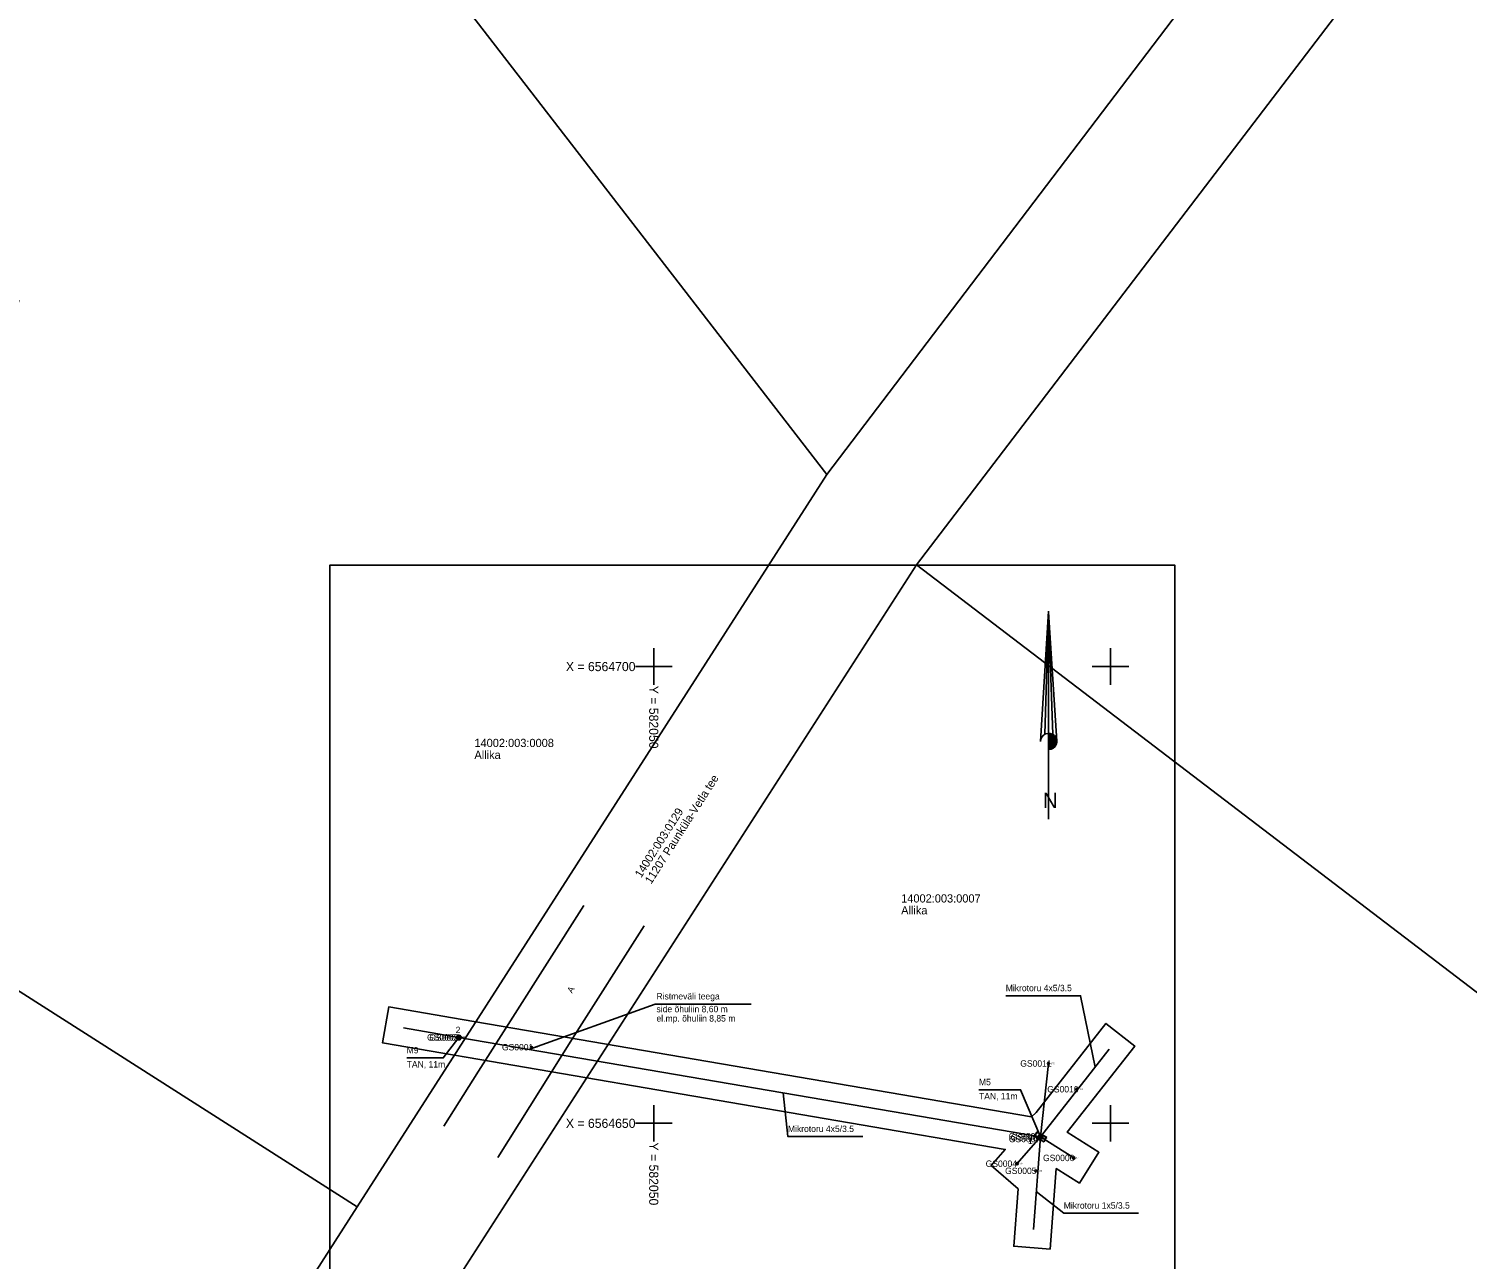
# Model space of a CAD drawing. Extents: x 579747 to 582499, y 6562295 to 6565613.
# Drawn here: x 581981.6 to 582139.1, y 6564635.1 to 6564769.8 of the extents above; entities that cross this region are included whole.
import ezdxf

# ---------------------------------------------------------------- set-up
doc = ezdxf.new("R2010")
doc.units = 0
for name, color, linetype in [('ABIJOONIS', 7, 'Continuous'), ('ELRAJATISMP', 7, 'Continuous'), ('KOORDPUNKT', 7, 'Continuous'), ('MOOTKORG-EH2000', 7, 'Continuous'), ('MOOTMPUNKT', 7, 'Continuous'), ('MOOTNR', 7, 'Continuous'), ('MOOTPIIR', 7, 'Continuous'), ('MPOHULIIN', 7, 'Continuous'), ('PIIR', 7, 'Continuous'), ('POST', 7, 'Continuous'), ('SIOHULIIN', 7, 'Continuous'), ('TEE', 7, 'Continuous'), ('VORK', 7, 'Continuous'), ('VORMISTUS', 7, 'Continuous')]:
    doc.layers.add(name, color=color, linetype=linetype)

msp = doc.modelspace()

# ---------------------------------------------------------------- linework, layer by layer
at = {"layer": 'ELRAJATISMP'}
for p, q in [((582092.36, 6564648.84), (582092.07, 6564648.33)), ((582092.6, 6564648.71), (582092.3, 6564648.19))]:
    msp.add_line(p, q, dxfattribs=at)
msp.add_lwpolyline([(582091.96, 6564649.07), (582093, 6564648.48), (582092.7, 6564647.96), (582091.67, 6564648.55)], close=True, dxfattribs=at)
at = {"layer": 'KOORDPUNKT'}
for centre, radius in [((582028.67, 6564659.4), 0.188), ((582028.67, 6564659.4), 0.0143), ((582028.67, 6564659.4), 0.0165), ((582028.67, 6564659.4), 0.0188), ((582028.67, 6564659.4), 0.00323), ((582028.67, 6564659.4), 0.00545), ((582028.67, 6564659.4), 0.00766), ((582028.67, 6564659.4), 0.00988), ((582028.67, 6564659.4), 0.0121), ((582092.33, 6564648.52), 0.188), ((582092.33, 6564648.52), 0.0188), ((582092.33, 6564648.52), 0.00988), ((582092.33, 6564648.52), 0.0121), ((582092.33, 6564648.52), 0.0143), ((582092.33, 6564648.52), 0.0165), ((582092.33, 6564648.52), 0.00766), ((582092.33, 6564648.52), 0.00323), ((582092.33, 6564648.52), 0.00545)]:
    msp.add_circle(centre, radius, dxfattribs=at)
at = {"layer": 'MOOTMPUNKT'}
for centre in [(582028.54, 6564659.41), (582028.67, 6564659.4), (582028.79, 6564659.39), (582036.6, 6564658.33), (582093.21, 6564656.55), (582096.3, 6564653.73), (582092.23, 6564648.59), (582092.24, 6564648.28), (582092.33, 6564648.52), (582092.44, 6564648.45), (582095.98, 6564646.21), (582089.76, 6564645.58), (582091.83, 6564644.8)]:
    msp.add_circle(centre, 0.1, dxfattribs=at)
at = {"layer": 'MOOTPIIR'}
msp.add_lwpolyline([(582029.01, 6564661.37), (582091.35, 6564650.72), (582091.87, 6564651.18), (582099.51, 6564660.93), (582102.66, 6564658.46), (582095.27, 6564649.03), (582098.74, 6564646.83), (582096.6, 6564643.45), (582094.07, 6564645.05), (582093.4, 6564636.23), (582089.41, 6564636.54), (582089.89, 6564642.81), (582086.94, 6564645.39), (582088.48, 6564647.15), (582020.31, 6564658.81), (582020.99, 6564662.75)], close=True, dxfattribs=at)
at = {"layer": 'MPOHULIIN'}
for p, q in [((582092.33, 6564648.52), (582099.85, 6564658.12)), ((582093.21, 6564656.55), (582092.33, 6564648.52)), ((582092.33, 6564648.52), (582091.56, 6564638.38))]:
    msp.add_line(p, q, dxfattribs=at)
msp.add_lwpolyline([(582092.33, 6564648.52), (582028.67, 6564659.4), (582022.62, 6564660.44)], dxfattribs=at)
at = {"layer": 'PIIR'}
for points in [[(581663.3, 6564864.5), (581668.6, 6564818), (581873.54, 6564758.6), (581980.49, 6564740.06), (581961.05, 6564676.89), (582017.54, 6564640.84), (582068.96, 6564721.02), (581983.85, 6564831.15), (581889.63, 6565244.18), (581674.18, 6565307.14)], [(582078.75, 6564711.15), (582029.16, 6564634.01), (582192.43, 6564520.86), (582199.06, 6564516.3), (582287.58, 6564527.55), (582301.82, 6564540.75), (582292.62, 6564547.98)]]:
    msp.add_lwpolyline(points, close=True, dxfattribs=at)
for points in [[(582135.55, 6564808.67), (582068.96, 6564721.02), (582017.54, 6564640.84), (581956.73, 6564546.01), (581888.98, 6564444.16), (581819.5, 6564352.29), (581772.04, 6564298.67), (581650.74, 6564171.18), (581565.74, 6564073.89), (581521.68, 6564027.95), (581462.2, 6563979.51), (581405.77, 6563949.46), (581387.54, 6563937.32), (581346.36, 6563914.86)], [(581384.59, 6563917.2), (581404.32, 6563931.05), (581456.61, 6563960.43), (581471.37, 6563968.93), (581531.08, 6564017.57), (581575.85, 6564064.19), (581579.4, 6564062.41), (581615.32, 6564103.23), (581653.52, 6564150.59), (581684.72, 6564185.3), (581762.65, 6564266.98), (581831.7, 6564341.91), (581902.22, 6564435.18), (581985.17, 6564563.48), (582029.16, 6564634.01), (582078.75, 6564711.15), (582146.74, 6564800.25)]]:
    msp.add_lwpolyline(points, dxfattribs=at)
at = {"layer": 'POST'}
for points in [[(582028.67, 6564659.4), (582026.95, 6564657.16), (582022.95, 6564657.16)], [(582092.33, 6564648.52), (582090.17, 6564653.67), (582085.61, 6564653.67)], [(582092.33, 6564648.52), (582089.76, 6564645.58)], [(582092.33, 6564648.52), (582095.98, 6564646.21)]]:
    msp.add_lwpolyline(points, dxfattribs=at)
for centre, radius in [((582028.67, 6564659.4), 0.25), ((582092.33, 6564648.52), 0.25), ((582095.98, 6564646.21), 0.125), ((582095.98, 6564646.21), 0.105), ((582095.98, 6564646.21), 0.0851), ((582095.98, 6564646.21), 0.0651), ((582095.98, 6564646.21), 0.0451), ((582095.98, 6564646.21), 0.0251), ((582095.98, 6564646.21), 0.00511), ((582089.76, 6564645.58), 0.125), ((582089.76, 6564645.58), 0.105), ((582089.76, 6564645.58), 0.0851), ((582089.76, 6564645.58), 0.0651), ((582089.76, 6564645.58), 0.0451), ((582089.76, 6564645.58), 0.0251), ((582089.76, 6564645.58), 0.00511)]:
    msp.add_circle(centre, radius, dxfattribs=at)
at = {"layer": 'SIOHULIIN'}
for p, q in [((582092.33, 6564648.52), (582099.85, 6564658.12)), ((582091.56, 6564638.38), (582092.33, 6564648.52))]:
    msp.add_line(p, q, dxfattribs=at)
for points in [[(582098.32, 6564656.16), (582096.73, 6564663.96), (582088.54, 6564663.96)], [(582036.33, 6564658.09), (582050.15, 6564663.06), (582060.68, 6564663.06)], [(582022.62, 6564660.44), (582028.67, 6564659.4), (582092.33, 6564648.52)], [(582064.17, 6564653.33), (582064.69, 6564648.55), (582072.88, 6564648.55)], [(582091.88, 6564642.54), (582094.89, 6564640.16), (582103.08, 6564640.16)]]:
    msp.add_lwpolyline(points, dxfattribs=at)
at = {"layer": 'TEE'}
for points in [[(582042.35, 6564673.85), (582030.81, 6564655.7), (582027.01, 6564649.67)], [(582032.93, 6564646.24), (582041.12, 6564659.29), (582048.95, 6564671.63)]]:
    msp.add_lwpolyline(points, dxfattribs=at)
at = {"layer": 'VORK'}
for p, q in [((582050, 6564702), (582050, 6564698)), ((582100, 6564702), (582100, 6564698)), ((582048, 6564700), (582052, 6564700)), ((582098, 6564700), (582102, 6564700)), ((582050, 6564652), (582050, 6564648)), ((582100, 6564652), (582100, 6564648)), ((582048, 6564650), (582052, 6564650)), ((582098, 6564650), (582102, 6564650))]:
    msp.add_line(p, q, dxfattribs=at)
at = {"layer": 'VORMISTUS'}
msp.add_lwpolyline([(582014.55, 6564568.11), (582014.55, 6564711.11), (582107.05, 6564711.11), (582107.05, 6564568.11)], close=True, dxfattribs=at)
for points in [[(582093.23, 6564706.06), (582092.33, 6564691.8)], [(582093.23, 6564705.96), (582092.81, 6564692.59)], [(582093.22, 6564706.01), (582093.69, 6564692.56)], [(582093.23, 6564706.06), (582093.23, 6564683.31)], [(582093.23, 6564705.95), (582094.12, 6564691.82)], [(582093.23, 6564692.69), (582093.27, 6564692.69)], [(582093.23, 6564692.69), (582093.25, 6564692.69)], [(582093.23, 6564692.59), (582093.66, 6564692.59)], [(582093.23, 6564692.48), (582093.8, 6564692.48)], [(582093.23, 6564692.38), (582093.89, 6564692.38)], [(582093.23, 6564692.28), (582093.97, 6564692.28)], [(582093.23, 6564692.17), (582094.03, 6564692.17)], [(582093.23, 6564692.07), (582094.07, 6564692.07)], [(582093.23, 6564691.97), (582094.1, 6564691.97)], [(582093.23, 6564691.86), (582094.11, 6564691.86)], [(582093.23, 6564691.76), (582094.12, 6564691.76)], [(582093.23, 6564691.66), (582094.1, 6564691.66)], [(582093.23, 6564691.56), (582094.08, 6564691.56)], [(582093.3, 6564690.92), (582093.3, 6564692.68)], [(582093.4, 6564690.94), (582093.4, 6564692.67)], [(582093.51, 6564690.95), (582093.51, 6564692.64)], [(582093.61, 6564691), (582093.61, 6564692.6)], [(582093.71, 6564691.06), (582093.71, 6564692.56)], [(582093.81, 6564691.14), (582093.81, 6564692.47)], [(582093.92, 6564691.24), (582093.92, 6564692.35)], [(582094.02, 6564691.41), (582094.02, 6564692.21)], [(582093.22, 6564690.94), (582093.42, 6564690.94)], [(582093.23, 6564691.45), (582094.04, 6564691.45)], [(582093.23, 6564691.35), (582093.99, 6564691.35)], [(582093.23, 6564691.25), (582093.92, 6564691.25)], [(582093.23, 6564691.14), (582093.82, 6564691.14)], [(582093.23, 6564691.04), (582093.68, 6564691.04)]]:
    msp.add_lwpolyline(points, dxfattribs=at)
msp.add_arc((582093.24, 6564691.8), 0.894, 270.3348, 180.6244, dxfattribs=at)

# ---------------------------------------------------------------- texts
at = {"layer": 'ABIJOONIS'}
for s, p in [(' 2', (582028.05, 6564659.87)), (' 1', (582090.71, 6564647.74))]:
    msp.add_text(s, height=0.7, dxfattribs=at).set_placement(p)
at = {"layer": 'MOOTKORG-EH2000'}
for s, p in [(' 64.84', (582028.54, 6564659.33)), (' 64.83', (582028.67, 6564659.31)), (' 64.82', (582028.79, 6564659.3)), (' 64.89', (582036.6, 6564658.24)), (' 64.79', (582093.21, 6564656.46)), (' 64.93', (582096.3, 6564653.64)), (' 64.97', (582092.23, 6564648.5)), (' 64.99', (582092.24, 6564648.19)), (' 64.99', (582092.33, 6564648.43)), (' 65.00', (582092.44, 6564648.36)), (' 64.91', (582095.98, 6564646.12)), (' 64.84', (582089.76, 6564645.5)), (' 64.83', (582091.83, 6564644.71))]:
    msp.add_text(s, height=0.175, dxfattribs=at).set_placement(p)
at = {"layer": 'MOOTNR'}
for s, p in [('GS0003 ', (582025.18, 6564659.06)), ('GS0002 ', (582025.43, 6564659.04)), ('GS0001 ', (582033.38, 6564657.98)), ('GS0011 ', (582090.13, 6564656.2)), ('GS0010 ', (582093.08, 6564653.38)), ('GS0009 ', (582088.87, 6564648.24)), ('GS0007 ', (582088.88, 6564647.93)), ('GS0008 ', (582089.08, 6564648.1)), ('GS0004 ', (582086.34, 6564645.23)), ('GS0006 ', (582092.62, 6564645.86)), ('GS0005 ', (582088.47, 6564644.45))]:
    msp.add_text(s, height=0.7, dxfattribs=at).set_placement(p)
at = {"layer": 'PIIR'}
for s, p in [('14002:003:0008', (582030.37, 6564691.19)), ('Allika', (582030.37, 6564689.89)), ('14002:003:0007', (582077.09, 6564674.17)), ('Allika', (582077.09, 6564672.87))]:
    msp.add_text(s, height=0.9, dxfattribs=at).set_placement(p)
for s, p in [('11207 Paunküla-Vetla tee', (582049.72, 6564676.12)), ('14002:003:0129', (582048.62, 6564676.81))]:
    msp.add_text(s, height=0.9, rotation=57.5293, dxfattribs=at).set_placement(p)
at = {"layer": 'POST'}
for s, p in [('M9', (582022.95, 6564657.66)), ('TAN, 11m', (582022.95, 6564656.11)), ('M5', (582085.61, 6564654.17)), ('TAN, 11m', (582085.61, 6564652.62))]:
    msp.add_text(s, height=0.7, dxfattribs=at).set_placement(p)
at = {"layer": 'SIOHULIIN'}
for s, p in [('Mikrotoru 4x5/3.5', (582088.54, 6564664.46)), ('Ristmeväli teega', (582050.3, 6564663.56)), ('side õhuliin 8,60 m', (582050.3, 6564662.16)), ('el.mp. õhuliin 8,85 m', (582050.3, 6564661.14)), ('Mikrotoru 4x5/3.5', (582064.69, 6564649.05)), ('Mikrotoru 1x5/3.5', (582094.89, 6564640.66))]:
    msp.add_text(s, height=0.7, dxfattribs=at).set_placement(p)
at = {"layer": 'TEE'}
msp.add_text('A', height=0.7, rotation=58.9351, dxfattribs=at).set_placement((582041.06, 6564664.19))
at = {"layer": 'VORK'}
for s, p in [('X = 6564700', (582040.38, 6564699.5)), ('X = 6564650', (582040.38, 6564649.5))]:
    msp.add_text(s, height=1, dxfattribs=at).set_placement(p)
for p in [(582049.5, 6564697.9), (582049.5, 6564647.9)]:
    msp.add_text('Y = 582050', height=1, rotation=270, dxfattribs=at).set_placement(p)
at = {"layer": 'VORMISTUS'}
msp.add_text('N', height=1.67, dxfattribs=at).set_placement((582092.61, 6564684.51))

doc.saveas('drawing.dxf')
